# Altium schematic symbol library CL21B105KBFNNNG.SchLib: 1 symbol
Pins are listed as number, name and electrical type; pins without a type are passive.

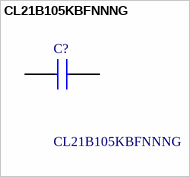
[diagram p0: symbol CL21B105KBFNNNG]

## CL21B105KBFNNNG
designator C?
Cap Ceramic 1uF 50V X7R 10% Pad SMD 0805 125C T/R; Manufacturer_Name: SAMSUNG; Geometry.Height: 1.35mm
footprint CAPC2012X135N
pins: 1, 2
